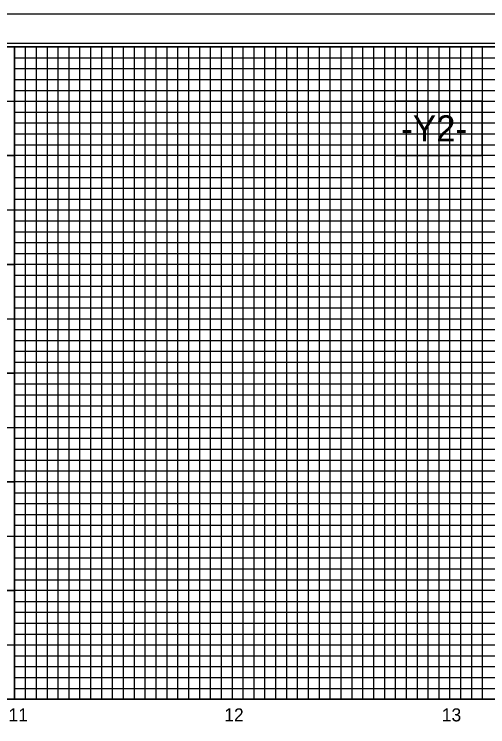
# Model space of a CAD drawing. Extents: x 270 to 1290, y -4845 to -4185.
# Drawn here: x 850 to 1067.5, y -4512.4 to -4184.8 of the extents above; entities that cross this region are included whole.
import ezdxf

# ---------------------------------------------------------------- set-up
doc = ezdxf.new("R2010")
doc.units = 0
for name, color, linetype in [('Exist Vertical Profile Horizontal Axis Label Major', 7, 'Continuous'), ('Prop Grid Mask', 7, 'Continuous'), ('Prop PFL Text', 7, 'Continuous'), ('Scratch_Level_1', 7, 'Continuous'), ('Sheet Cutting Line CELL', 7, 'Continuous'), ('Sheet Layout Profile Border Port 1', 7, 'Continuous'), ('Sheet Plot Border Inside CELL', 7, 'Continuous'), ('Sheet Plot Border Outside CELL', 7, 'Continuous'), ('Sheet Profile CELL', 7, 'Continuous'), ('Sheet Profile Grid Major CELL', 7, 'Continuous'), ('Sheet Profile Grid Middle CELL', 7, 'Continuous'), ('Sheet Profile Grid Minor CELL', 7, 'Continuous')]:
    doc.layers.add(name, color=color, linetype=linetype)

msp = doc.modelspace()

# ---------------------------------------------------------------- linework, layer by layer
at = {"layer": 'Prop Grid Mask'}
msp.add_lwpolyline([(1025, -4249.75), (1065, -4249.75), (1065, -4224.75), (1025, -4224.75)], close=True, dxfattribs=at)
at = {"layer": 'Prop PFL Text'}
msp.add_lwpolyline([(1025, -4249.75), (1065, -4249.75), (1065, -4224.75), (1025, -4224.75)], close=True, dxfattribs=at)
at = {"layer": 'Scratch_Level_1'}
msp.add_lwpolyline([(850, -4199.75), (1240, -4199.75), (1240, -4499.75), (850, -4499.75)], close=True, dxfattribs=at)
at = {"layer": 'Sheet Cutting Line CELL'}
msp.add_line((1289.8, -4184.75), (269.8, -4184.75), dxfattribs=at)
at = {"layer": 'Sheet Layout Profile Border Port 1'}
msp.add_lwpolyline([(400, -4199.75), (1149.97, -4199.75), (1149.97, -4319.63), (1240, -4319.75), (1240, -4499.75), (400, -4499.75)], close=True, dxfattribs=at)
at = {"layer": 'Sheet Plot Border Inside CELL'}
msp.add_lwpolyline([(277.6, -4831.28), (1277.5, -4831.28), (1277.5, -4198.22), (277.6, -4198.22)], close=True, dxfattribs=at)
at = {"layer": 'Sheet Plot Border Outside CELL'}
msp.add_lwpolyline([(269.8, -4844.75), (1289.8, -4844.75), (1289.8, -4184.75), (269.8, -4184.75)], close=True, dxfattribs=at)
at = {"layer": 'Sheet Profile CELL'}
msp.add_line((370, -4499.75), (1270, -4499.75), dxfattribs=at)
msp.add_lwpolyline([(1270, -4199.75), (370, -4199.75), (370, -4829.75), (1270, -4829.75)], close=True, dxfattribs=at)
at = {"layer": 'Sheet Profile Grid Major CELL'}
for p, q in [((850, -4199.75), (850, -4499.75)), ((875, -4199.75), (875, -4499.75)), ((900, -4199.75), (900, -4499.75)), ((925, -4199.75), (925, -4499.75)), ((950, -4199.75), (950, -4499.75)), ((975, -4199.75), (975, -4499.75)), ((1000, -4199.75), (1000, -4499.75)), ((1025, -4199.75), (1025, -4499.75)), ((1050, -4199.75), (1050, -4499.75)), ((370, -4224.75), (1150, -4224.75)), ((800, -4224.75), (850, -4224.75)), ((1150, -4249.75), (370, -4249.75)), ((800, -4249.75), (850, -4249.75)), ((370, -4274.75), (1150, -4274.75)), ((800, -4274.75), (850, -4274.75)), ((1150, -4299.75), (370, -4299.75)), ((800, -4299.75), (850, -4299.75)), ((370, -4324.75), (1270, -4324.75)), ((800, -4324.75), (850, -4324.75)), ((1270, -4349.75), (370, -4349.75)), ((800, -4349.75), (850, -4349.75)), ((370, -4374.75), (1270, -4374.75)), ((800, -4374.75), (850, -4374.75)), ((1270, -4399.75), (370, -4399.75)), ((800, -4399.75), (850, -4399.75)), ((370, -4424.75), (1270, -4424.75)), ((800, -4424.75), (850, -4424.75)), ((1270, -4449.75), (370, -4449.75)), ((800, -4449.75), (850, -4449.75)), ((370, -4474.75), (1270, -4474.75))]:
    msp.add_line(p, q, dxfattribs=at)
at = {"layer": 'Sheet Profile Grid Middle CELL'}
for p, q in [((850, -4204.75), (1150, -4204.75)), ((850, -4209.75), (1150, -4209.75)), ((850, -4214.75), (1150, -4214.75)), ((850, -4219.75), (1150, -4219.75)), ((850, -4229.75), (1150, -4229.75)), ((850, -4234.75), (1150, -4234.75)), ((850, -4239.75), (1150, -4239.75)), ((850, -4244.75), (1150, -4244.75)), ((850, -4254.75), (1150, -4254.75)), ((850, -4259.75), (1150, -4259.75)), ((850, -4264.75), (1150, -4264.75)), ((850, -4269.75), (1150, -4269.75)), ((850, -4279.75), (1150, -4279.75)), ((850, -4284.75), (1150, -4284.75)), ((850, -4289.75), (1150, -4289.75)), ((850, -4294.75), (1150, -4294.75)), ((850, -4304.75), (1150, -4304.75)), ((850, -4309.75), (1150, -4309.75)), ((850, -4314.75), (1150, -4314.75)), ((850, -4319.75), (1240, -4319.75)), ((850, -4329.75), (1240, -4329.75)), ((850, -4334.75), (1240, -4334.75)), ((850, -4339.75), (1240, -4339.75)), ((850, -4344.75), (1240, -4344.75)), ((850, -4354.75), (1240, -4354.75)), ((850, -4359.75), (1240, -4359.75)), ((850, -4364.75), (1240, -4364.75)), ((850, -4369.75), (1240, -4369.75)), ((850, -4379.75), (1240, -4379.75)), ((850, -4384.75), (1240, -4384.75)), ((850, -4389.75), (1240, -4389.75)), ((850, -4394.75), (1240, -4394.75)), ((850, -4404.75), (1240, -4404.75)), ((850, -4409.75), (1240, -4409.75)), ((850, -4414.75), (1240, -4414.75)), ((850, -4419.75), (1240, -4419.75)), ((850, -4429.75), (1240, -4429.75)), ((850, -4434.75), (1240, -4434.75)), ((850, -4439.75), (1240, -4439.75)), ((850, -4444.75), (1240, -4444.75)), ((850, -4454.75), (1240, -4454.75)), ((850, -4459.75), (1240, -4459.75)), ((850, -4464.75), (1240, -4464.75)), ((850, -4469.75), (1240, -4469.75)), ((850, -4479.75), (1240, -4479.75)), ((850, -4484.75), (1240, -4484.75)), ((850, -4489.75), (1240, -4489.75)), ((850, -4494.75), (1240, -4494.75))]:
    msp.add_line(p, q, dxfattribs=at)
at = {"layer": 'Sheet Profile Grid Minor CELL'}
for p, q in [((855, -4199.75), (855, -4499.75)), ((860, -4199.75), (860, -4499.75)), ((865, -4199.75), (865, -4499.75)), ((870, -4199.75), (870, -4499.75)), ((880, -4199.75), (880, -4499.75)), ((885, -4199.75), (885, -4499.75)), ((890, -4199.75), (890, -4499.75)), ((895, -4199.75), (895, -4499.75)), ((905, -4199.75), (905, -4499.75)), ((910, -4199.75), (910, -4499.75)), ((915, -4199.75), (915, -4499.75)), ((920, -4199.75), (920, -4499.75)), ((930, -4199.75), (930, -4499.75)), ((935, -4199.75), (935, -4499.75)), ((940, -4199.75), (940, -4499.75)), ((945, -4199.75), (945, -4499.75)), ((955, -4199.75), (955, -4499.75)), ((960, -4199.75), (960, -4499.75)), ((965, -4199.75), (965, -4499.75)), ((970, -4199.75), (970, -4499.75)), ((980, -4199.75), (980, -4499.75)), ((985, -4199.75), (985, -4499.75)), ((990, -4199.75), (990, -4499.75)), ((995, -4199.75), (995, -4499.75)), ((1005, -4199.75), (1005, -4499.75)), ((1010, -4199.75), (1010, -4499.75)), ((1015, -4199.75), (1015, -4499.75)), ((1020, -4199.75), (1020, -4499.75)), ((1030, -4199.75), (1030, -4499.75)), ((1035, -4199.75), (1035, -4499.75)), ((1040, -4199.75), (1040, -4499.75)), ((1045, -4199.75), (1045, -4499.75)), ((1055, -4199.75), (1055, -4499.75)), ((1060, -4199.75), (1060, -4499.75)), ((1065, -4199.75), (1065, -4499.75))]:
    msp.add_line(p, q, dxfattribs=at)

# ---------------------------------------------------------------- texts
at = {"layer": 'Exist Vertical Profile Horizontal Axis Label Major'}
for s, p in [('11', (847.3, -4509.93)), ('12', (946.44, -4509.93)), ('13', (1046.4, -4509.93))]:
    msp.add_text(s, height=6, dxfattribs=at).set_placement(p)
at = {"layer": 'Prop PFL Text'}
msp.add_text('-Y2-', height=12, dxfattribs=at).set_placement((1027.75, -4243.25))

doc.saveas('drawing.dxf')
